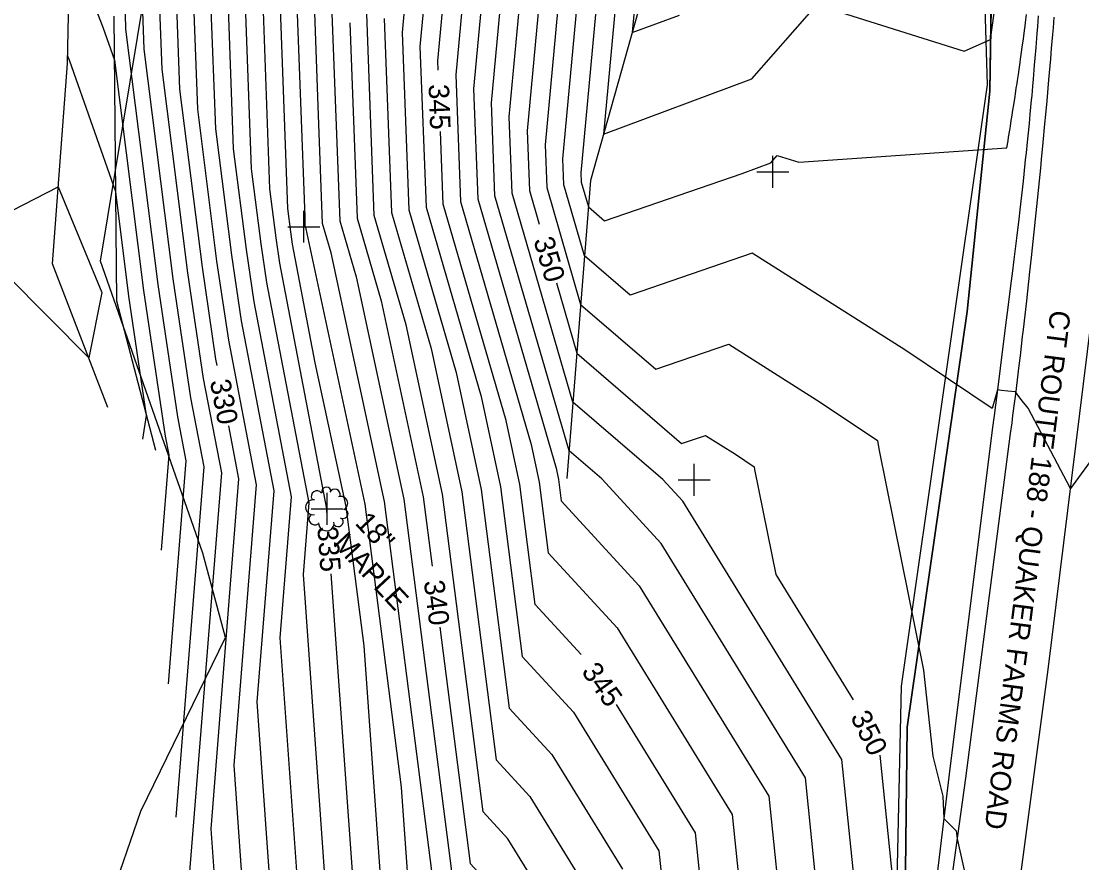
# Model space of a CAD drawing. Extents: x 487096 to 489566, y 221939 to 224454.
# Drawn here: x 488276.8 to 488442.7, y 223219.9 to 223351.6 of the extents above; entities that cross this region are included whole.
import ezdxf

# ---------------------------------------------------------------- set-up
doc = ezdxf.new("R2010")
doc.units = 0
for name, color, linetype in [('SV_BKLN_BKLN', 7, 'Continuous'), ('SV_BKLN_EARTH_TOP', 7, 'Continuous'), ('SV_FENC_FENCES', 7, 'Continuous'), ('SV_ROAD_BITRD', 7, 'Continuous'), ('SV_ROWL_HWYLOC', 7, 'Continuous'), ('SV_ROWL_ROWL_TX', 7, 'Continuous'), ('SV_SURF_INDEX_CONTOUR', 7, 'Continuous'), ('SV_SURF_INTER_CONTOUR', 7, 'Continuous'), ('SV_SURF_SPOT', 7, 'Continuous'), ('SV_TRAF_PVMTL', 7, 'Continuous'), ('SV_TREE_TREEVEG', 7, 'Continuous'), ('SV_TREE_TREEVEG_TX', 7, 'Continuous'), ('SV_WATR_INWETF', 7, 'Continuous'), ('SV_WATR_STREAM', 7, 'Continuous')]:
    doc.layers.add(name, color=color, linetype=linetype)

msp = doc.modelspace()

# ---------------------------------------------------------------- linework, layer by layer
at = {"layer": 'SV_BKLN_BKLN'}
msp.add_lwpolyline([(488290.36, 223291.11), (488281.66, 223313.59), (488284.01, 223344.96), (488284.69, 223377.57)], dxfattribs=at)
at = {"layer": 'SV_BKLN_EARTH_TOP'}
for points in [[(488395.68, 223500.35), (488384.29, 223433.52), (488381.81, 223383.31), (488365.84, 223326.63), (488362.14, 223280.01)], [(488428.29, 223340.61), (488429.01, 223386.27)]]:
    msp.add_lwpolyline(points, dxfattribs=at)
at = {"layer": 'SV_FENC_FENCES'}
msp.add_lwpolyline([(488415.01, 223209.78), (488415.39, 223241.14), (488424.74, 223306.14), (488428.29, 223340.61), (488429.01, 223386.27)], dxfattribs=at)
at = {"layer": 'SV_ROAD_BITRD'}
msp.add_lwpolyline([(488435.87, 223352.39), (488435.75, 223350.74), (488435.67, 223349.65), (488435.56, 223348.18), (488435.5, 223347.45), (488435.37, 223345.8), (488435.27, 223344.7), (488435.15, 223343.24), (488435.09, 223342.51), (488434.99, 223341.41), (488434.86, 223339.95), (488434.79, 223339.22), (488434.59, 223337.02), (488434.45, 223335.56), (488434.25, 223333.61), (488434.15, 223332.64), (488433.98, 223330.97), (488433.86, 223329.86), (488433.62, 223327.63), (488433.5, 223326.52), (488433.25, 223324.29), (488433, 223322.07), (488432.83, 223320.59), (488432.48, 223317.63), (488432.07, 223314.29), (488431.8, 223312.07), (488431.62, 223310.59), (488431.25, 223307.63), (488430.68, 223303.19), (488429.93, 223297.27), (488429.55, 223294.3), (488428.98, 223289.86), (488428.7, 223287.64), (488421.94, 223233.77), (488416.24, 223186.63)], dxfattribs=at)
msp.add_lwpolyline([(488435.87, 223352.39), (488435.75, 223350.74), (488435.67, 223349.65), (488435.56, 223348.18), (488435.5, 223347.45), (488435.37, 223345.8), (488435.27, 223344.7), (488435.15, 223343.24), (488435.09, 223342.51), (488434.99, 223341.41), (488434.86, 223339.95), (488434.79, 223339.22), (488434.59, 223337.02), (488434.45, 223335.56), (488434.25, 223333.61), (488434.15, 223332.64), (488433.98, 223330.97), (488433.86, 223329.86), (488433.62, 223327.63), (488433.5, 223326.52), (488433.25, 223324.29), (488433, 223322.07), (488432.83, 223320.59), (488432.48, 223317.63), (488432.07, 223314.29), (488431.8, 223312.07), (488431.62, 223310.59), (488431.25, 223307.63), (488430.68, 223303.19), (488429.93, 223297.27), (488429.55, 223294.3), (488428.98, 223289.86), (488428.7, 223287.64), (488421.94, 223233.77), (488416.24, 223186.63)], dxfattribs=at)
msp.add_lwpolyline([(488435.87, 223352.39), (488435.75, 223350.74), (488435.67, 223349.65), (488435.56, 223348.18), (488435.5, 223347.45), (488435.37, 223345.8), (488435.27, 223344.7), (488435.15, 223343.24), (488435.09, 223342.51), (488434.99, 223341.41), (488434.86, 223339.95), (488434.79, 223339.22), (488434.59, 223337.02), (488434.45, 223335.56), (488434.25, 223333.61), (488434.15, 223332.64), (488433.98, 223330.97), (488433.86, 223329.86), (488433.62, 223327.63), (488433.5, 223326.52), (488433.25, 223324.29), (488433, 223322.07), (488432.83, 223320.59), (488432.48, 223317.63), (488432.07, 223314.29), (488431.8, 223312.07), (488431.62, 223310.59), (488431.25, 223307.63), (488430.68, 223303.19), (488429.93, 223297.27), (488429.55, 223294.3), (488428.98, 223289.86), (488428.7, 223287.64), (488421.94, 223233.77), (488416.24, 223186.63)], dxfattribs=at)
at = {"layer": 'SV_ROWL_HWYLOC'}
msp.add_lwpolyline([(488362.04, 223571.42), (488379.11, 223558.17), (488393.88, 223539.38), (488394.74, 223535.64), (488413.01, 223498.44), (488420.16, 223469.81), (488427.32, 223441.18), (488428.59, 223411.48), (488428.89, 223402.56), (488428.65, 223363.44), (488428.29, 223340.61), (488424.74, 223306.14), (488415.39, 223241.14), (488415.01, 223209.78)], dxfattribs=at)
at = {"layer": 'SV_SURF_INDEX_CONTOUR'}
for points in [[(488342.02, 223343.88), (488341.96, 223345.38), (488343.87, 223365.98), (488347.24, 223392.36), (488349.16, 223415.47), (488350.44, 223429.15), (488350.51, 223429.83)], [(488362.96, 223405.65), (488362.63, 223402.2), (488361.51, 223388.63), (488359.53, 223373.13), (488355.94, 223334.4), (488356.29, 223325.09), (488357.82, 223319.83)], [(488377.7, 223405.89), (488376.11, 223388.93), (488375.78, 223384.89), (488375.19, 223380.29), (488372.36, 223349.77), (488379.74, 223352.51)], [(488307.44, 223297.68), (488307.25, 223298.67), (488305.12, 223313.11), (488301.59, 223340.94), (488301.12, 223353.92), (488296.52, 223371.33), (488297.58, 223379.75), (488297.69, 223383)], [(488313.45, 223360.04), (488314.51, 223356.03), (488315.63, 223325.35), (488316.6, 223317.68), (488317.19, 223313.69), (488324.56, 223275.31), (488324.53, 223274.99), (488324.55, 223274.7)], [(488328.17, 223351.33), (488329.32, 223320.76), (488333.08, 223307.83), (488339.67, 223277.18), (488341.06, 223266.29)], [(488295.82, 223286.2), (488296.39, 223289.9), (488293.64, 223308.54), (488291.57, 223324.85), (488284.37, 223345.33), (488284.03, 223346.2)], [(488364.38, 223252.5), (488357.19, 223260.32), (488354.79, 223279.08), (488352.64, 223289.11), (488342.81, 223322.93), (488342.38, 223334.29)], [(488360.5, 223310.61), (488363.7, 223299.61), (488380.09, 223285.5), (488383.83, 223286.78), (488388.51, 223283.82), (488391.45, 223281.84), (488391.51, 223281.42), (488394.84, 223264.99), (488406.91, 223245.39)], [(488310.47, 223202.71), (488307.47, 223211.35), (488306.48, 223225.22), (488310.84, 223279.98), (488309.25, 223288.25)], [(488325.23, 223265.13), (488329.34, 223207.61), (488333.25, 223196.36), (488335.38, 223179.67)], [(488342.28, 223256.77), (488347.01, 223219.79), (488349.5, 223217.08), (488353.65, 223210.35), (488354.1, 223205.9), (488354.27, 223202.43), (488354.27, 223202.11), (488354.27, 223201.89), (488354.26, 223201.45), (488354.26, 223201.23), (488354.25, 223200.78), (488361.53, 223173.86)], [(488388.03, 223162.47), (488388.47, 223170.46), (488388.52, 223171.69), (488388.6, 223173.52), (488384.55, 223188.46), (488384.58, 223190.14), (488384.6, 223190.97), (488384.61, 223192.64), (488384.62, 223193.46), (488384.62, 223194.7), (488384, 223207.81), (488382.28, 223224.63), (488369.93, 223244.67)], [(488411.12, 223236.77), (488413.89, 223209.71), (488414.98, 223186.96), (488414.97, 223184.82), (488414.96, 223183.38), (488414.93, 223180.5), (488414.91, 223179.05), (488414.86, 223176.14), (488414.87, 223176.1), (488414.84, 223175.35), (488414.95, 223173.76), (488414.98, 223173.2), (488415.06, 223172.01), (488415.1, 223171.25), (488415.17, 223169.84), (488415.28, 223167.35), (488415.29, 223167.1), (488415.31, 223166.55), (488415.7, 223164.29), (488415.96, 223162.61), (488416.11, 223161.55), (488418.21, 223150.91)]]:
    msp.add_lwpolyline(points, dxfattribs=at)
at = {"layer": 'SV_SURF_INTER_CONTOUR'}
for points in [[(488346.36, 223521.53), (488346.85, 223494.01), (488346.93, 223493.81), (488347.81, 223455.85), (488346.83, 223451.21), (488344.48, 223428.39), (488343.76, 223420.78), (488341.54, 223393.86), (488337.6, 223363.12), (488336.37, 223349.78), (488337.41, 223322.06), (488344.81, 223296.59), (488348.74, 223278.32), (488353.12, 223244.11), (488359.77, 223236.87), (488370.82, 223218.92)], [(488350.31, 223519.83), (488350.76, 223494.52), (488350.84, 223494.33), (488351.64, 223459.42), (488349.63, 223449.88), (488347.46, 223428.77), (488346.46, 223418.13), (488344.39, 223393.11), (488340.74, 223364.55), (488339.16, 223347.58), (488340.11, 223322.49), (488348.72, 223292.85), (488351.77, 223278.7), (488355.16, 223252.21), (488363.19, 223243.47), (488376.55, 223221.78), (488378.02, 223207.43)], [(488407.91, 223209.33), (488405.18, 223236.05), (488380.3, 223276.46), (488377.15, 223279.88), (488363.09, 223291.99), (488353.59, 223324.66), (488353.14, 223336.6), (488356.4, 223371.7), (488358.66, 223389.38), (488359.94, 223404.85), (488362.36, 223430.69), (488363.65, 223443.26), (488370.82, 223477.24), (488370.37, 223496.95), (488370.32, 223497.06), (488370.07, 223511.35), (488377.87, 223520.35)], [(488358.21, 223516.44), (488358.59, 223495.54), (488358.65, 223495.38), (488359.31, 223466.55), (488355.24, 223447.24), (488353.42, 223429.54), (488351.85, 223412.82), (488350.1, 223391.62), (488347, 223367.41), (488344.76, 223343.19), (488345.5, 223323.36), (488356.55, 223285.36), (488357.81, 223279.46), (488359.23, 223268.42), (488370.03, 223256.66), (488388, 223227.49), (488389.98, 223208.19)], [(488362.16, 223514.74), (488362.5, 223496.04), (488362.56, 223495.9), (488363.15, 223470.11), (488358.04, 223445.91), (488356.4, 223429.92), (488354.55, 223410.16), (488352.95, 223390.87), (488350.13, 223368.84), (488347.55, 223340.99), (488348.2, 223323.79), (488360.46, 223281.62), (488360.84, 223279.85), (488361.26, 223276.53), (488373.45, 223263.26), (488393.73, 223230.34), (488395.96, 223208.57)], [(488401.94, 223208.95), (488399.45, 223233.2), (488376.88, 223269.86), (488367.59, 223279.96), (488362.48, 223284.36), (488350.9, 223324.23), (488350.35, 223338.8), (488353.26, 223370.27), (488355.8, 223390.12), (488357.24, 223407.51), (488359.38, 223430.31), (488360.85, 223444.59), (488366.98, 223473.68), (488366.46, 223496.43), (488366.41, 223496.55), (488366.12, 223513.04)], [(488320.59, 223209.11), (488317.31, 223255.08), (488319.07, 223277.18), (488313.22, 223307.68), (488312.01, 223315.85), (488310.01, 223331.59), (488309.15, 223355.18), (488306.03, 223366.99), (488308.32, 223385.06), (488309.64, 223426.75), (488310.11, 223434.83), (488310.42, 223440), (488309.76, 223461.16), (488307.73, 223462.23), (488308.95, 223474.1), (488303.64, 223466.04), (488302.9, 223468.7), (488298.73, 223458.51), (488295.43, 223452.1), (488285.67, 223455.59), (488279.11, 223460.73), (488240.25, 223486.42)], [(488316.22, 223209.85), (488313.7, 223245.12), (488316.33, 223278.11), (488311.23, 223304.68), (488309.71, 223314.94), (488307.21, 223334.7), (488306.47, 223354.76), (488302.86, 223368.44), (488304.74, 223383.29), (488306.27, 223431.43), (488306.52, 223435.82), (488306.69, 223438.63), (488306.33, 223450.11), (488303.27, 223451.72), (488303.93, 223458.21), (488301.03, 223453.81), (488299.83, 223458.17), (488296.58, 223450.25), (488292.12, 223441.58), (488285.76, 223443.86), (488281.49, 223447.21), (488226.84, 223483.32)], [(488311.84, 223210.6), (488310.09, 223235.17), (488313.58, 223279.04), (488309.24, 223301.67), (488307.41, 223314.02), (488304.4, 223337.82), (488303.8, 223354.34), (488299.69, 223369.89), (488301.16, 223381.52), (488302.89, 223436.11), (488302.93, 223436.81), (488302.96, 223437.25), (488302.9, 223439.06), (488298.8, 223441.21), (488298.91, 223442.32), (488298.41, 223441.57), (488296.75, 223447.63), (488294.44, 223442), (488288.8, 223431.07), (488285.85, 223432.12), (488283.87, 223433.68), (488213.44, 223480.22)], [(488288.19, 223421.7), (488290.14, 223425.49), (488290.59, 223426.57), (488290.96, 223425.23), (488293.34, 223414.09), (488294.47, 223413.48), (488294.84, 223404.29), (488294.01, 223377.98), (488293.35, 223372.78), (488298.44, 223353.49), (488298.78, 223344.06), (488302.82, 223312.2), (488305.27, 223295.66), (488308.1, 223280.91), (488302.87, 223215.26)], [(488290.13, 223398.93), (488290.43, 223394.13), (488290.75, 223386.25), (488290.43, 223376.21), (488290.18, 223374.22), (488295.76, 223353.07), (488295.98, 223347.17), (488300.52, 223311.28), (488303.28, 223292.66), (488305.35, 223281.84), (488300.99, 223227.03)], [(488299.83, 223247.93), (488302.61, 223282.78), (488301.29, 223289.65), (488298.23, 223310.37), (488293.17, 223350.29), (488293.08, 223352.65), (488289.35, 223366.81), (488286.01, 223376.65), (488285.7, 223381.54)], [(488372.06, 223378.86), (488367.89, 223333.91), (488391.07, 223342.52), (488401.23, 223354.12), (488424.28, 223346.87), (488428.42, 223348.68), (488432.16, 223375.78)], [(488368.92, 223377.43), (488364.33, 223327.82), (488364.38, 223326.39), (488365.51, 223322.5), (488368.02, 223320.34), (488389.58, 223327.76), (488394.04, 223329.42), (488395.04, 223330.57), (488398.43, 223329.5), (488430.98, 223331.76), (488431.16, 223332.84), (488431.25, 223333.4), (488431.44, 223334.54), (488431.53, 223335.12), (488431.67, 223336.01), (488431.75, 223336.54), (488431.92, 223337.63), (488432.05, 223338.47), (488432.25, 223339.76), (488432.32, 223340.2), (488432.45, 223341.11), (488432.56, 223341.8), (488432.63, 223342.27), (488432.77, 223343.24), (488432.88, 223343.98), (488433.04, 223345.12), (488433.11, 223345.64), (488433.26, 223346.7), (488433.38, 223347.52), (488433.55, 223348.78), (488433.61, 223349.22), (488433.73, 223350.09), (488433.82, 223350.77), (488433.9, 223351.38), (488434.06, 223352.62)], [(488445.28, 223284.43), (488440.92, 223278.47), (488434.33, 223291.04), (488433.88, 223291.54), (488433.56, 223291.93), (488432.85, 223292.85), (488432.46, 223293.4), (488432.34, 223293.58), (488431.1, 223293.7), (488430.15, 223293.8), (488429.49, 223293.9), (488428.69, 223290.96), (488415.01, 223300.14), (488391.12, 223315.3), (488372.04, 223308.73), (488364.91, 223314.87), (488361.69, 223325.96), (488361.53, 223330.01), (488365.79, 223376)], [(488362.66, 223374.56), (488358.74, 223332.21), (488358.99, 223325.53), (488364.3, 223307.24), (488376.07, 223297.11), (488387.47, 223301.04), (488401.76, 223291.98), (488410.73, 223285.96), (488410.93, 223284.66), (488417.94, 223250.06), (488419.41, 223236.62), (488420.94, 223230.33), (488421.1, 223226.85), (488423.04, 223224.94), (488423.18, 223223.68), (488426.18, 223210.38)], [(488284.41, 223363.91), (488289.57, 223350.61), (488291.37, 223345.48), (488295.93, 223309.45), (488299.3, 223286.65), (488299.87, 223283.71), (488298.68, 223268.82)], [(488342.16, 223209.67), (488333.62, 223276.41), (488325.26, 223315.32), (488323.93, 223319.89), (488323.29, 223336.84), (488322.54, 223357.3)], [(488324.97, 223208.36), (488320.92, 223265.03), (488321.81, 223276.24), (488315.2, 223310.69), (488314.3, 223316.76), (488312.82, 223328.47), (488311.83, 223355.61)], [(488317.19, 223356.45), (488318.43, 223322.24), (488318.9, 223318.59), (488319.18, 223316.7), (488322.74, 223298.12), (488327.57, 223275.65), (488330.36, 223253.85), (488333.72, 223206.86)], [(488338.09, 223206.12), (488336.26, 223231.76), (488330.6, 223276.03), (488321.35, 223319.06), (488321.23, 223319.46), (488321.18, 223320.94), (488319.86, 223356.87)], [(488359.37, 223213.21), (488352.93, 223223.68), (488349.05, 223227.9), (488342.69, 223277.56), (488336.99, 223304.08), (488332.02, 223321.19), (488330.78, 223354.17)], [(488325.4, 223352.75), (488326.63, 223320.33), (488329.17, 223311.57), (488336.64, 223276.8), (488344.98, 223211.69)], [(488333.57, 223351.97), (488334.72, 223321.63), (488340.9, 223300.34), (488345.72, 223277.94), (488351.08, 223236), (488356.35, 223230.28), (488365.1, 223216.06)]]:
    msp.add_lwpolyline(points, dxfattribs=at)
msp.add_lwpolyline([(488282.56, 223325.64), (488289.42, 223309.12), (488287.36, 223298.88), (488268.14, 223318.26)], close=True, dxfattribs=at)
at = {"layer": 'SV_SURF_SPOT'}
for p, q in [((488394.37, 223325.49), (488394.37, 223330.49)), ((488391.87, 223327.99), (488396.87, 223327.99)), ((488394.37, 223327.99), (488394.37, 223327.99)), ((488320.97, 223316.92), (488320.97, 223321.92)), ((488318.47, 223319.42), (488323.48, 223319.42)), ((488320.97, 223319.42), (488320.97, 223319.42)), ((488382.05, 223277.34), (488382.05, 223282.34)), ((488379.55, 223279.84), (488384.55, 223279.84)), ((488382.05, 223279.84), (488382.05, 223279.84)), ((488324.64, 223272.78), (488324.64, 223277.78)), ((488322.14, 223275.28), (488327.14, 223275.28)), ((488324.64, 223275.28), (488324.64, 223275.28))]:
    msp.add_line(p, q, dxfattribs=at)
at = {"layer": 'SV_TRAF_PVMTL'}
for points in [[(488428.31, 223181.75), (488437.42, 223250.14), (488444.19, 223304.94), (488449.14, 223354.51)], [(488438.33, 223352.18), (488438.2, 223350.54), (488438.11, 223349.46), (488437.93, 223347.28), (488437.79, 223345.65), (488437.7, 223344.56), (488437.51, 223342.38), (488437.22, 223339.12), (488437.02, 223336.94), (488436.88, 223335.49), (488436.61, 223332.59), (488436.35, 223329.92), (488436.22, 223328.59), (488436.02, 223326.59), (488435.72, 223323.59), (488435.41, 223320.59), (488435.26, 223319.09), (488434.94, 223316.09), (488434.78, 223314.59), (488434.53, 223312.34), (488434.2, 223309.34), (488434.03, 223307.84), (488433.78, 223305.59), (488433.52, 223303.34), (488433.39, 223302.22), (488433.03, 223299.22), (488432.85, 223297.73), (488432.58, 223295.48), (488432.3, 223293.23), (488432.16, 223292.11), (488431.87, 223289.87), (488431.73, 223288.74), (488431.51, 223287.06), (488424.5, 223233.13), (488417.97, 223186.18)]]:
    msp.add_lwpolyline(points, dxfattribs=at)
at = {"layer": 'SV_TREE_TREEVEG'}
msp.add_line((488324.64, 223275.28), (488324.64, 223275.28), dxfattribs=at)
msp.add_lwpolyline([(488469.57, 222626.73), (488414.36, 222775.8), (488391.31, 222875.65), (488384.76, 223013.78), (488396.28, 223079.01), (488413.65, 223210.14), (488414.48, 223247.55), (488427.96, 223341.62), (488424.88, 223443.61), (488411.44, 223499.76), (488395.39, 223528.76), (488373.34, 223524.5)], dxfattribs=at)
for centre, radius, start, end in [((488323.03, 223277.24), 0.874, 35.9933, 211.459), ((488324.53, 223277.93), 0.75, 23.2911, 192.3579), ((488325.84, 223277.52), 0.85, 345.5308, 152.7093), ((488322.44, 223275.53), 1.17, 79.3292, 279.9889), ((488326.8, 223276.16), 1.06, 294.1859, 111.1082), ((488322.72, 223273.68), 0.922, 137.0157, 304.5501)]:
    msp.add_arc(centre, radius, start, end, dxfattribs=at)
for centre, major_axis, ratio, start_param, end_param in [((488327.09, 223274.51), (0.822, -0.013), 0.901056, 4.216583, 7.444153), ((488324.51, 223272.95), (-1.2, 0.16), 0.902156, 0, 3.5401), ((488326.36, 223273.31), (0.08, -0.798), 0.999752, 5.391582, 8.241319)]:
    msp.add_ellipse(centre, major_axis=major_axis, ratio=ratio, start_param=start_param, end_param=end_param, dxfattribs=at)
at = {"layer": 'SV_WATR_INWETF'}
msp.add_lwpolyline([(488252.55, 223050.25), (488264.25, 223090.23), (488281.91, 223135.61), (488282.57, 223190.44), (488295.5, 223227.97), (488308.75, 223255.15), (488305.2, 223268.34), (488289.17, 223314.01), (488298.4, 223369.86), (488304.63, 223422.7), (488301.31, 223432.19)], dxfattribs=at)
at = {"layer": 'SV_WATR_STREAM'}
msp.add_lwpolyline([(488297.82, 223284.41), (488291.74, 223307.79), (488291.3, 223352.37)], dxfattribs=at)

# ---------------------------------------------------------------- texts
at = {"layer": 'SV_ROWL_ROWL_TX'}
msp.add_text('CT ROUTE 188 - QUAKER FARMS ROAD', height=3.2, rotation=262.7443, dxfattribs=at).set_placement((488437.81, 223306.48))
at = {"layer": 'SV_SURF_INDEX_CONTOUR'}
for s, rotation, p in [('345', 272.1601, (488340.5, 223341.67)), ('350', 286.2044, (488356.89, 223317.32)), ('330', 280.8632, (488306.28, 223295.26)), ('335', 274.0869, (488323.11, 223272.45)), ('340', 277.2926, (488339.75, 223263.95)), ('345', 305.3727, (488364.32, 223249.82)), ('350', 296.1484, (488406.43, 223242.76))]:
    msp.add_text(s, height=3.2, rotation=rotation, dxfattribs=at).set_placement(p)
at = {"layer": 'SV_TREE_TREEVEG_TX'}
for s, p in [('18"', (488328.86, 223272.96)), ('MAPLE', (488325.42, 223269.75))]:
    msp.add_text(s, height=3.2, rotation=313.0386, dxfattribs=at).set_placement(p)

doc.saveas('drawing.dxf')
